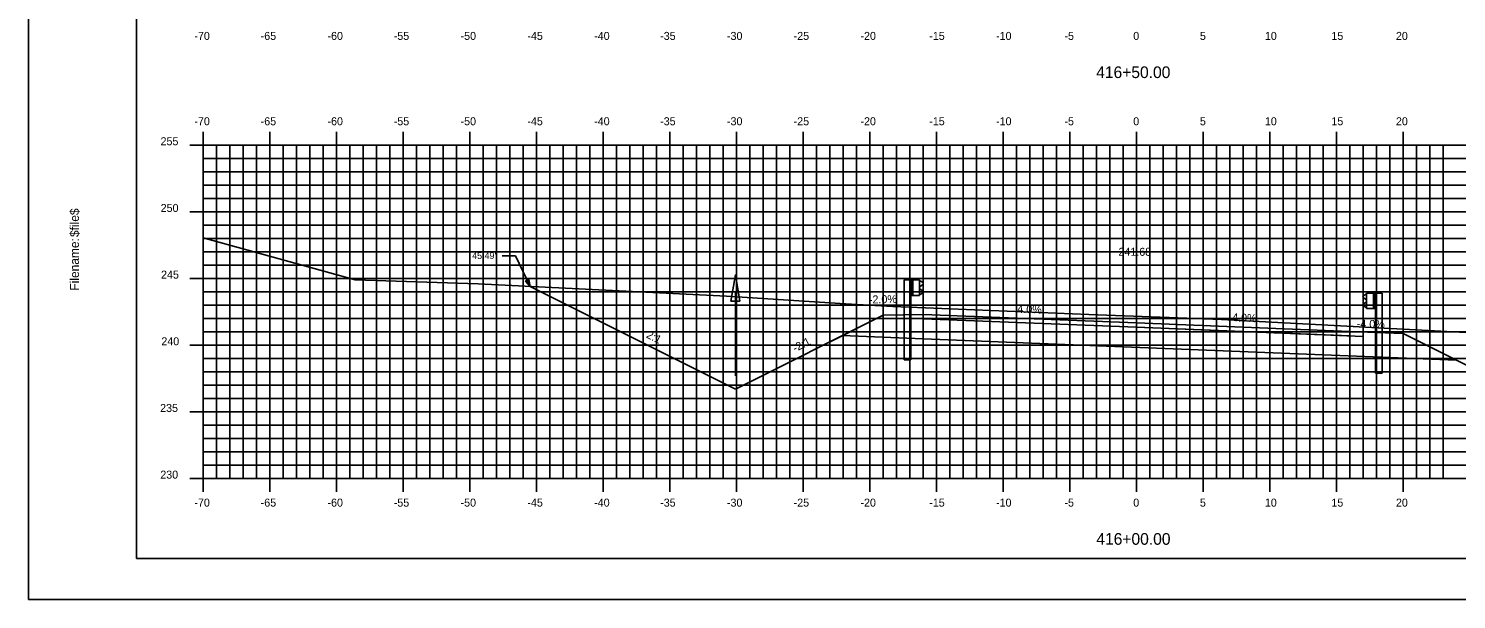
# Model space of a CAD drawing. Extents: x 1160718 to 1173142, y 616002 to 617630.
# Drawn here: x 1168548.8 to 1168655.8, y 616613.9 to 616656.7 of the extents above; entities that cross this region are included whole.
import ezdxf

# ---------------------------------------------------------------- set-up
doc = ezdxf.new("R2010")
doc.units = 0
for name, color, linetype in [('ANNOTATION', 7, 'Continuous'), ('BORDER', 7, 'Continuous'), ('D_Drainage_Ditch_Line', 7, 'Continuous'), ('D_Guardrail_Beam_Lt', 7, 'Continuous'), ('D_Guardrail_Beam_Rt', 7, 'Continuous'), ('D_Roadway_Centerline', 7, 'Continuous'), ('D_Roadway_Centerline_Text', 7, 'Continuous'), ('D_Roadway_Edge_Shoulder', 7, 'Continuous'), ('D_Roadway_Edge_TW', 7, 'Continuous'), ('D_Roadway_Pavement', 7, 'Continuous'), ('D_Roadway_SlopeLines', 7, 'Continuous'), ('D_Roadway_SubGrade', 7, 'Continuous'), ('H_V ANNOTATION', 7, 'Continuous'), ('MAJOR', 7, 'Continuous'), ('MINOR', 7, 'Continuous'), ('PLOT BOUNDARY', 7, 'Continuous'), ('S_Roadway_Centerline', 7, 'Continuous'), ('SHADING', 7, 'Continuous')]:
    doc.layers.add(name, color=color, linetype=linetype)

msp = doc.modelspace()

# ---------------------------------------------------------------- linework, layer by layer
at = {"layer": 'ANNOTATION'}
for p, q in [((1168584.27, 616639.65), (1168585.27, 616639.65)), ((1168586.37, 616637.35), (1168585.27, 616639.65)), ((1168647.85, 616633.97), (1168651.85, 616633.81))]:
    msp.add_line(p, q, dxfattribs=at)
msp.add_lwpolyline([(1168586.27, 616637.86), (1168586.37, 616637.35), (1168586.04, 616637.75)], close=True, dxfattribs=at)
at = {"layer": 'BORDER'}
for p, q in [((1168556.85, 616721.93), (1168556.85, 616616.93)), ((1168556.85, 616616.93), (1168716.85, 616616.93))]:
    msp.add_line(p, q, dxfattribs=at)
at = {"layer": 'D_Drainage_Ditch_Line'}
msp.add_line((1168601.77, 616636.9), (1168601.77, 616630.65), dxfattribs=at)
msp.add_lwpolyline([(1168602.1, 616636.24), (1168601.44, 616636.24), (1168601.77, 616638.21)], close=True, dxfattribs=at)
at = {"layer": 'D_Guardrail_Beam_Lt'}
for p, q in [((1168614.43, 616637.83), (1168614.43, 616631.83)), ((1168614.9, 616637.83), (1168614.43, 616637.83)), ((1168615.59, 616637.83), (1168614.9, 616637.83)), ((1168614.9, 616637.83), (1168614.9, 616636.67)), ((1168614.96, 616637.83), (1168614.96, 616636.67)), ((1168615.07, 616637.83), (1168615.07, 616636.67)), ((1168615.59, 616636.67), (1168615.59, 616637.83)), ((1168615.59, 616637.75), (1168615.66, 616637.74)), ((1168615.59, 616637.29), (1168615.59, 616637.22)), ((1168615.82, 616637.49), (1168615.62, 616637.35)), ((1168615.62, 616637.15), (1168615.82, 616637.01)), ((1168615.68, 616637.73), (1168615.82, 616637.63)), ((1168615.82, 616636.87), (1168615.68, 616636.77)), ((1168614.9, 616636.67), (1168615.59, 616636.67)), ((1168614.92, 616631.83), (1168614.92, 616636.67)), ((1168615.66, 616636.77), (1168615.59, 616636.75)), ((1168614.92, 616631.83), (1168614.43, 616631.83))]:
    msp.add_line(p, q, dxfattribs=at)
for centre, major_axis, start_param, end_param in [((1168615.67, 616637.29), (-0.0789, 0), 5.323254, 6.283185), ((1168615.67, 616637.22), (-0.0789, 0), 6.283185, 7.243116), ((1168615.65, 616637.7), (0.0417, 0), 0.959931, 1.376053), ((1168615.77, 616637.56), (0.0877, 0), 5.323254, 7.243116), ((1168615.77, 616636.94), (0.0877, 0), 5.323254, 7.243116), ((1168615.65, 616636.81), (0.0417, 0), 4.907132, 5.323254)]:
    msp.add_ellipse(centre, major_axis=major_axis, ratio=0.995501, start_param=start_param, end_param=end_param, dxfattribs=at)
at = {"layer": 'D_Guardrail_Beam_Rt'}
for p, q in [((1168649.11, 616636.85), (1168649.8, 616636.85)), ((1168649.11, 616635.68), (1168649.11, 616636.85)), ((1168649.63, 616636.85), (1168649.63, 616635.68)), ((1168649.73, 616636.85), (1168649.73, 616635.68)), ((1168649.8, 616636.85), (1168650.27, 616636.85)), ((1168649.8, 616636.85), (1168649.8, 616635.68)), ((1168650.27, 616636.85), (1168650.27, 616630.85)), ((1168649.02, 616636.75), (1168648.87, 616636.65)), ((1168648.87, 616636.5), (1168649.07, 616636.37)), ((1168649.07, 616636.17), (1168648.87, 616636.03)), ((1168648.87, 616635.89), (1168649.02, 616635.79)), ((1168649.11, 616636.77), (1168649.03, 616636.75)), ((1168649.03, 616635.78), (1168649.11, 616635.77)), ((1168649.1, 616636.3), (1168649.1, 616636.23)), ((1168649.8, 616635.68), (1168649.11, 616635.68)), ((1168649.77, 616630.85), (1168649.77, 616635.68)), ((1168649.77, 616630.85), (1168650.27, 616630.85))]:
    msp.add_line(p, q, dxfattribs=at)
for centre, major_axis, start_param, end_param in [((1168648.92, 616636.57), (-0.0877, 0), 5.323254, 7.243116), ((1168648.92, 616635.96), (-0.0877, 0), 5.323254, 7.243116), ((1168649.04, 616636.71), (-0.0417, 0), 4.907132, 5.323254), ((1168649.04, 616635.82), (-0.0417, 0), 0.959931, 1.376053), ((1168649.02, 616636.3), (0.0789, 0), 0, 0.959931), ((1168649.02, 616636.23), (0.0789, 0), 5.323254, 6.283185)]:
    msp.add_ellipse(centre, major_axis=major_axis, ratio=0.995501, start_param=start_param, end_param=end_param, dxfattribs=at)
at = {"layer": 'D_Roadway_Edge_Shoulder'}
msp.add_lwpolyline([(1168615.85, 616635.25), (1168615.85, 616634.92)], dxfattribs=at)
at = {"layer": 'D_Roadway_Edge_TW'}
for p, q in [((1168615.85, 616634.92), (1168615.85, 616635.25)), ((1168615.85, 616635.25), (1168631.85, 616634.61)), ((1168631.85, 616634.28), (1168615.85, 616634.92)), ((1168631.85, 616634.61), (1168647.85, 616633.97)), ((1168648.85, 616633.6), (1168631.85, 616634.28))]:
    msp.add_line(p, q, dxfattribs=at)
at = {"layer": 'D_Roadway_Pavement'}
msp.add_lwpolyline([(1168615.85, 616634.92), (1168615.85, 616634.92), (1168631.85, 616634.28), (1168647.85, 616633.64), (1168647.85, 616633.64), (1168631.85, 616634.28)], close=True, dxfattribs=at)
for points in [[(1168615.85, 616634.92), (1168615.85, 616634.92)], [(1168615.85, 616634.92), (1168615.85, 616634.92)], [(1168647.85, 616633.64), (1168647.85, 616633.64)], [(1168647.85, 616633.64), (1168647.85, 616633.64)]]:
    msp.add_lwpolyline(points, dxfattribs=at)
at = {"layer": 'D_Roadway_SlopeLines'}
for points in [[(1168601.77, 616629.65), (1168586.37, 616637.35)], [(1168612.85, 616635.19), (1168601.77, 616629.65)], [(1168651.85, 616633.81), (1168662.93, 616628.27)]]:
    msp.add_lwpolyline(points, dxfattribs=at)
at = {"layer": 'D_Roadway_SubGrade'}
for p, q in [((1168612.85, 616635.19), (1168608.87, 616633.2)), ((1168615.85, 616635.25), (1168612.85, 616635.19)), ((1168615.85, 616633.42), (1168615.85, 616635.25)), ((1168615.85, 616633.42), (1168615.85, 616634.92)), ((1168615.85, 616634.92), (1168631.85, 616634.28)), ((1168631.85, 616634.28), (1168647.85, 616633.64)), ((1168648.85, 616632.1), (1168648.85, 616633.93))]:
    msp.add_line(p, q, dxfattribs=at)
at = {"layer": 'MAJOR'}
for p, q in [((1168561.85, 616648.93), (1168561.85, 616647.93)), ((1168566.85, 616648.93), (1168566.85, 616647.93)), ((1168571.85, 616648.93), (1168571.85, 616647.93)), ((1168576.85, 616648.93), (1168576.85, 616647.93)), ((1168581.85, 616648.93), (1168581.85, 616647.93)), ((1168586.85, 616648.93), (1168586.85, 616647.93)), ((1168591.85, 616648.93), (1168591.85, 616647.93)), ((1168596.85, 616648.93), (1168596.85, 616647.93)), ((1168601.85, 616648.93), (1168601.85, 616647.93)), ((1168606.85, 616648.93), (1168606.85, 616647.93)), ((1168611.85, 616648.93), (1168611.85, 616647.93)), ((1168616.85, 616648.93), (1168616.85, 616647.93)), ((1168621.85, 616648.93), (1168621.85, 616647.93)), ((1168626.85, 616648.93), (1168626.85, 616647.93)), ((1168631.85, 616648.93), (1168631.85, 616647.93)), ((1168636.85, 616648.93), (1168636.85, 616647.93)), ((1168641.85, 616648.93), (1168641.85, 616647.93)), ((1168646.85, 616648.93), (1168646.85, 616647.93)), ((1168651.85, 616648.93), (1168651.85, 616647.93)), ((1168560.85, 616647.93), (1168561.85, 616647.93)), ((1168561.85, 616647.93), (1168701.85, 616647.93)), ((1168561.85, 616622.93), (1168561.85, 616647.93)), ((1168561.85, 616622.93), (1168561.85, 616647.93)), ((1168561.85, 616647.93), (1168701.85, 616647.93)), ((1168566.85, 616622.93), (1168566.85, 616647.93)), ((1168571.85, 616622.93), (1168571.85, 616647.93)), ((1168576.85, 616622.93), (1168576.85, 616647.93)), ((1168581.85, 616622.93), (1168581.85, 616647.93)), ((1168586.85, 616622.93), (1168586.85, 616647.93)), ((1168591.85, 616622.93), (1168591.85, 616647.93)), ((1168596.85, 616622.93), (1168596.85, 616647.93)), ((1168601.85, 616622.93), (1168601.85, 616647.93)), ((1168606.85, 616622.93), (1168606.85, 616647.93)), ((1168611.85, 616622.93), (1168611.85, 616647.93)), ((1168616.85, 616622.93), (1168616.85, 616647.93)), ((1168621.85, 616622.93), (1168621.85, 616647.93)), ((1168626.85, 616622.93), (1168626.85, 616647.93)), ((1168631.85, 616622.93), (1168631.85, 616647.93)), ((1168636.85, 616622.93), (1168636.85, 616647.93)), ((1168641.85, 616622.93), (1168641.85, 616647.93)), ((1168646.85, 616622.93), (1168646.85, 616647.93)), ((1168651.85, 616622.93), (1168651.85, 616647.93)), ((1168560.85, 616642.93), (1168561.85, 616642.93)), ((1168561.85, 616642.93), (1168701.85, 616642.93)), ((1168560.85, 616637.93), (1168561.85, 616637.93)), ((1168561.85, 616637.93), (1168701.85, 616637.93)), ((1168560.85, 616632.93), (1168561.85, 616632.93)), ((1168561.85, 616632.93), (1168701.85, 616632.93)), ((1168560.85, 616627.93), (1168561.85, 616627.93)), ((1168561.85, 616627.93), (1168701.85, 616627.93)), ((1168560.85, 616622.93), (1168561.85, 616622.93)), ((1168561.85, 616622.93), (1168701.85, 616622.93)), ((1168561.85, 616622.93), (1168701.85, 616622.93)), ((1168561.85, 616621.93), (1168561.85, 616622.93)), ((1168566.85, 616621.93), (1168566.85, 616622.93)), ((1168571.85, 616621.93), (1168571.85, 616622.93)), ((1168576.85, 616621.93), (1168576.85, 616622.93)), ((1168581.85, 616621.93), (1168581.85, 616622.93)), ((1168586.85, 616621.93), (1168586.85, 616622.93)), ((1168591.85, 616621.93), (1168591.85, 616622.93)), ((1168596.85, 616621.93), (1168596.85, 616622.93)), ((1168601.85, 616621.93), (1168601.85, 616622.93)), ((1168606.85, 616621.93), (1168606.85, 616622.93)), ((1168611.85, 616621.93), (1168611.85, 616622.93)), ((1168616.85, 616621.93), (1168616.85, 616622.93)), ((1168621.85, 616621.93), (1168621.85, 616622.93)), ((1168626.85, 616621.93), (1168626.85, 616622.93)), ((1168631.85, 616621.93), (1168631.85, 616622.93)), ((1168636.85, 616621.93), (1168636.85, 616622.93)), ((1168641.85, 616621.93), (1168641.85, 616622.93)), ((1168646.85, 616621.93), (1168646.85, 616622.93)), ((1168651.85, 616621.93), (1168651.85, 616622.93))]:
    msp.add_line(p, q, dxfattribs=at)
at = {"layer": 'MINOR'}
for p, q in [((1168562.85, 616622.93), (1168562.85, 616647.93)), ((1168563.85, 616622.93), (1168563.85, 616647.93)), ((1168564.85, 616622.93), (1168564.85, 616647.93)), ((1168565.85, 616622.93), (1168565.85, 616647.93)), ((1168567.85, 616622.93), (1168567.85, 616647.93)), ((1168568.85, 616622.93), (1168568.85, 616647.93)), ((1168569.85, 616622.93), (1168569.85, 616647.93)), ((1168570.85, 616622.93), (1168570.85, 616647.93)), ((1168572.85, 616622.93), (1168572.85, 616647.93)), ((1168573.85, 616622.93), (1168573.85, 616647.93)), ((1168574.85, 616622.93), (1168574.85, 616647.93)), ((1168575.85, 616622.93), (1168575.85, 616647.93)), ((1168577.85, 616622.93), (1168577.85, 616647.93)), ((1168578.85, 616622.93), (1168578.85, 616647.93)), ((1168579.85, 616622.93), (1168579.85, 616647.93)), ((1168580.85, 616622.93), (1168580.85, 616647.93)), ((1168582.85, 616622.93), (1168582.85, 616647.93)), ((1168583.85, 616622.93), (1168583.85, 616647.93)), ((1168584.85, 616622.93), (1168584.85, 616647.93)), ((1168585.85, 616622.93), (1168585.85, 616647.93)), ((1168587.85, 616622.93), (1168587.85, 616647.93)), ((1168588.85, 616622.93), (1168588.85, 616647.93)), ((1168589.85, 616622.93), (1168589.85, 616647.93)), ((1168590.85, 616622.93), (1168590.85, 616647.93)), ((1168592.85, 616622.93), (1168592.85, 616647.93)), ((1168593.85, 616622.93), (1168593.85, 616647.93)), ((1168594.85, 616622.93), (1168594.85, 616647.93)), ((1168595.85, 616622.93), (1168595.85, 616647.93)), ((1168597.85, 616622.93), (1168597.85, 616647.93)), ((1168598.85, 616622.93), (1168598.85, 616647.93)), ((1168599.85, 616622.93), (1168599.85, 616647.93)), ((1168600.85, 616622.93), (1168600.85, 616647.93)), ((1168602.85, 616622.93), (1168602.85, 616647.93)), ((1168603.85, 616622.93), (1168603.85, 616647.93)), ((1168604.85, 616622.93), (1168604.85, 616647.93)), ((1168605.85, 616622.93), (1168605.85, 616647.93)), ((1168607.85, 616622.93), (1168607.85, 616647.93)), ((1168608.85, 616622.93), (1168608.85, 616647.93)), ((1168609.85, 616622.93), (1168609.85, 616647.93)), ((1168610.85, 616622.93), (1168610.85, 616647.93)), ((1168612.85, 616622.93), (1168612.85, 616647.93)), ((1168613.85, 616622.93), (1168613.85, 616647.93)), ((1168614.85, 616622.93), (1168614.85, 616647.93)), ((1168615.85, 616622.93), (1168615.85, 616647.93)), ((1168617.85, 616622.93), (1168617.85, 616647.93)), ((1168618.85, 616622.93), (1168618.85, 616647.93)), ((1168619.85, 616622.93), (1168619.85, 616647.93)), ((1168620.85, 616622.93), (1168620.85, 616647.93)), ((1168622.85, 616622.93), (1168622.85, 616647.93)), ((1168623.85, 616622.93), (1168623.85, 616647.93)), ((1168624.85, 616622.93), (1168624.85, 616647.93)), ((1168625.85, 616622.93), (1168625.85, 616647.93)), ((1168627.85, 616622.93), (1168627.85, 616647.93)), ((1168628.85, 616622.93), (1168628.85, 616647.93)), ((1168629.85, 616622.93), (1168629.85, 616647.93)), ((1168630.85, 616622.93), (1168630.85, 616647.93)), ((1168632.85, 616622.93), (1168632.85, 616647.93)), ((1168633.85, 616622.93), (1168633.85, 616647.93)), ((1168634.85, 616622.93), (1168634.85, 616647.93)), ((1168635.85, 616622.93), (1168635.85, 616647.93)), ((1168637.85, 616622.93), (1168637.85, 616647.93)), ((1168638.85, 616622.93), (1168638.85, 616647.93)), ((1168639.85, 616622.93), (1168639.85, 616647.93)), ((1168640.85, 616622.93), (1168640.85, 616647.93)), ((1168642.85, 616622.93), (1168642.85, 616647.93)), ((1168643.85, 616622.93), (1168643.85, 616647.93)), ((1168644.85, 616622.93), (1168644.85, 616647.93)), ((1168645.85, 616622.93), (1168645.85, 616647.93)), ((1168647.85, 616622.93), (1168647.85, 616647.93)), ((1168648.85, 616622.93), (1168648.85, 616647.93)), ((1168649.85, 616622.93), (1168649.85, 616647.93)), ((1168650.85, 616622.93), (1168650.85, 616647.93)), ((1168652.85, 616622.93), (1168652.85, 616647.93)), ((1168653.85, 616622.93), (1168653.85, 616647.93)), ((1168654.85, 616622.93), (1168654.85, 616647.93)), ((1168561.85, 616646.93), (1168701.85, 616646.93)), ((1168561.85, 616646.93), (1168562.86, 616646.93)), ((1168561.85, 616645.93), (1168701.85, 616645.93)), ((1168561.85, 616645.93), (1168562.86, 616645.93)), ((1168561.85, 616644.93), (1168701.85, 616644.93)), ((1168561.85, 616644.93), (1168562.86, 616644.93)), ((1168561.85, 616643.93), (1168701.85, 616643.93)), ((1168561.85, 616643.93), (1168562.86, 616643.93)), ((1168561.85, 616641.93), (1168701.85, 616641.93)), ((1168561.85, 616641.93), (1168562.86, 616641.93)), ((1168561.85, 616640.93), (1168701.85, 616640.93)), ((1168561.85, 616640.93), (1168562.86, 616640.93)), ((1168561.85, 616639.93), (1168701.85, 616639.93)), ((1168561.85, 616639.93), (1168562.86, 616639.93)), ((1168561.85, 616638.93), (1168701.85, 616638.93)), ((1168561.85, 616638.93), (1168562.86, 616638.93)), ((1168561.85, 616636.93), (1168701.85, 616636.93)), ((1168561.85, 616636.93), (1168562.86, 616636.93)), ((1168561.85, 616635.93), (1168701.85, 616635.93)), ((1168561.85, 616635.93), (1168562.86, 616635.93)), ((1168561.85, 616634.93), (1168701.85, 616634.93)), ((1168561.85, 616634.93), (1168562.86, 616634.93)), ((1168561.85, 616633.93), (1168701.85, 616633.93)), ((1168561.85, 616633.93), (1168562.86, 616633.93)), ((1168561.85, 616631.93), (1168701.85, 616631.93)), ((1168561.85, 616631.93), (1168562.86, 616631.93)), ((1168561.85, 616630.93), (1168701.85, 616630.93)), ((1168561.85, 616630.93), (1168562.86, 616630.93)), ((1168561.85, 616629.93), (1168701.85, 616629.93)), ((1168561.85, 616629.93), (1168562.86, 616629.93)), ((1168561.85, 616628.93), (1168701.85, 616628.93)), ((1168561.85, 616628.93), (1168562.86, 616628.93)), ((1168561.85, 616626.93), (1168701.85, 616626.93)), ((1168561.85, 616626.93), (1168562.86, 616626.93)), ((1168561.85, 616625.93), (1168701.85, 616625.93)), ((1168561.85, 616625.93), (1168562.86, 616625.93)), ((1168561.85, 616624.93), (1168701.85, 616624.93)), ((1168561.85, 616624.93), (1168562.86, 616624.93)), ((1168561.85, 616623.93), (1168701.85, 616623.93)), ((1168561.85, 616623.93), (1168562.86, 616623.93))]:
    msp.add_line(p, q, dxfattribs=at)
at = {"layer": 'PLOT BOUNDARY'}
msp.add_lwpolyline([(1168548.76, 616613.87), (1168718.76, 616613.87), (1168718.76, 616723.87), (1168548.76, 616723.87)], close=True, dxfattribs=at)
at = {"layer": 'S_Roadway_Centerline'}
msp.add_lwpolyline([(1168561.85, 616641), (1168573.26, 616637.85), (1168582.48, 616637.54), (1168601.11, 616636.61), (1168610.04, 616636.05), (1168613.57, 616635.85), (1168628.29, 616635.25), (1168635.63, 616634.97), (1168638.22, 616634.86), (1168660.29, 616633.7), (1168663.94, 616633.71), (1168680.17, 616633.1), (1168682.7, 616632.58), (1168690.04, 616631.91), (1168695.26, 616633.48), (1168701.85, 616635.42)], dxfattribs=at)
at = {"layer": 'SHADING'}
msp.add_lwpolyline([(1168609.79, 616633.66), (1168615.85, 616633.42), (1168655.84, 616631.82)], dxfattribs=at)

# ---------------------------------------------------------------- texts
at = {"layer": 'ANNOTATION'}
msp.add_text("45.49'", height=0.5, dxfattribs=at).set_placement((1168582.03, 616639.4))
for s, rotation, p in [('-2.0%', 1.1458, (1168611.79, 616636.06)), ('4.0%', 357.7094, (1168622.91, 616635.37)), ('-4.0%', 357.7094, (1168638.75, 616634.74)), ('-4.0%', 358.8542, (1168648.37, 616634.25)), ('2:1', 333.4349, (1168595.04, 616633.53)), ('-2:1', 26.5651, (1168606.24, 616632.4))]:
    msp.add_text(s, height=0.6, rotation=rotation, dxfattribs=at).set_placement(p)
at = {"layer": 'BORDER'}
for s, p in [('$file$', (1168552.54, 616641.05)), ('Filename:', (1168552.54, 616637.03))]:
    msp.add_text(s, height=0.67, rotation=90, dxfattribs=at).set_placement(p)
at = {"layer": 'D_Roadway_Centerline'}
for s, p in [('C', (1168631.85, 616634.61)), ('L', (1168631.85, 616634.6))]:
    msp.add_text(s, height=0.0146, dxfattribs=at).set_placement(p)
at = {"layer": 'D_Roadway_Centerline_Text'}
msp.add_text('241.68', height=0.6, dxfattribs=at).set_placement((1168630.5, 616639.64))
at = {"layer": 'H_V ANNOTATION'}
for s, height, p in [('-70', 0.6, (1168561.2, 616655.83)), ('-65', 0.6, (1168566.17, 616655.83)), ('-60', 0.6, (1168571.18, 616655.83)), ('-55', 0.6, (1168576.15, 616655.83)), ('-50', 0.6, (1168581.16, 616655.83)), ('-45', 0.6, (1168586.17, 616655.83)), ('-40', 0.6, (1168591.18, 616655.83)), ('-35', 0.6, (1168596.13, 616655.83)), ('-30', 0.6, (1168601.14, 616655.83)), ('-25', 0.6, (1168606.14, 616655.83)), ('-20', 0.6, (1168611.15, 616655.83)), ('-15', 0.6, (1168616.31, 616655.83)), ('-10', 0.6, (1168621.32, 616655.83)), ('-5', 0.6, (1168626.45, 616655.83)), ('0', 0.6, (1168631.61, 616655.83)), ('5', 0.6, (1168636.61, 616655.83)), ('10', 0.6, (1168641.48, 616655.83)), ('15', 0.6, (1168646.47, 616655.83)), ('20', 0.6, (1168651.31, 616655.83)), ('416+50.00', 0.875, (1168628.83, 616652.97)), ('-70', 0.6, (1168561.2, 616649.43)), ('-65', 0.6, (1168566.17, 616649.43)), ('-60', 0.6, (1168571.18, 616649.43)), ('-55', 0.6, (1168576.15, 616649.43)), ('-50', 0.6, (1168581.16, 616649.43)), ('-45', 0.6, (1168586.17, 616649.43)), ('-40', 0.6, (1168591.18, 616649.43)), ('-35', 0.6, (1168596.13, 616649.43)), ('-30', 0.6, (1168601.14, 616649.43)), ('-25', 0.6, (1168606.14, 616649.43)), ('-20', 0.6, (1168611.15, 616649.43)), ('-15', 0.6, (1168616.31, 616649.43)), ('-10', 0.6, (1168621.32, 616649.43)), ('-5', 0.6, (1168626.45, 616649.43)), ('0', 0.6, (1168631.61, 616649.43)), ('5', 0.6, (1168636.61, 616649.43)), ('10', 0.6, (1168641.48, 616649.43)), ('15', 0.6, (1168646.47, 616649.43)), ('20', 0.6, (1168651.31, 616649.43)), ('255', 0.6, (1168558.66, 616647.93)), ('250', 0.6, (1168558.67, 616642.93)), ('245', 0.6, (1168558.7, 616637.93)), ('240', 0.6, (1168558.72, 616632.93)), ('235', 0.6, (1168558.63, 616627.93)), ('230', 0.6, (1168558.64, 616622.93)), ('-70', 0.6, (1168561.2, 616620.83)), ('-65', 0.6, (1168566.17, 616620.83)), ('-60', 0.6, (1168571.18, 616620.83)), ('-55', 0.6, (1168576.15, 616620.83)), ('-50', 0.6, (1168581.16, 616620.83)), ('-45', 0.6, (1168586.17, 616620.83)), ('-40', 0.6, (1168591.18, 616620.83)), ('-35', 0.6, (1168596.13, 616620.83)), ('-30', 0.6, (1168601.14, 616620.83)), ('-25', 0.6, (1168606.14, 616620.83)), ('-20', 0.6, (1168611.15, 616620.83)), ('-15', 0.6, (1168616.31, 616620.83)), ('-10', 0.6, (1168621.32, 616620.83)), ('-5', 0.6, (1168626.45, 616620.83)), ('0', 0.6, (1168631.61, 616620.83)), ('5', 0.6, (1168636.61, 616620.83)), ('10', 0.6, (1168641.48, 616620.83)), ('15', 0.6, (1168646.47, 616620.83)), ('20', 0.6, (1168651.31, 616620.83)), ('416+00.00', 0.875, (1168628.84, 616617.97))]:
    msp.add_text(s, height=height, dxfattribs=at).set_placement(p)

doc.saveas('drawing.dxf')
